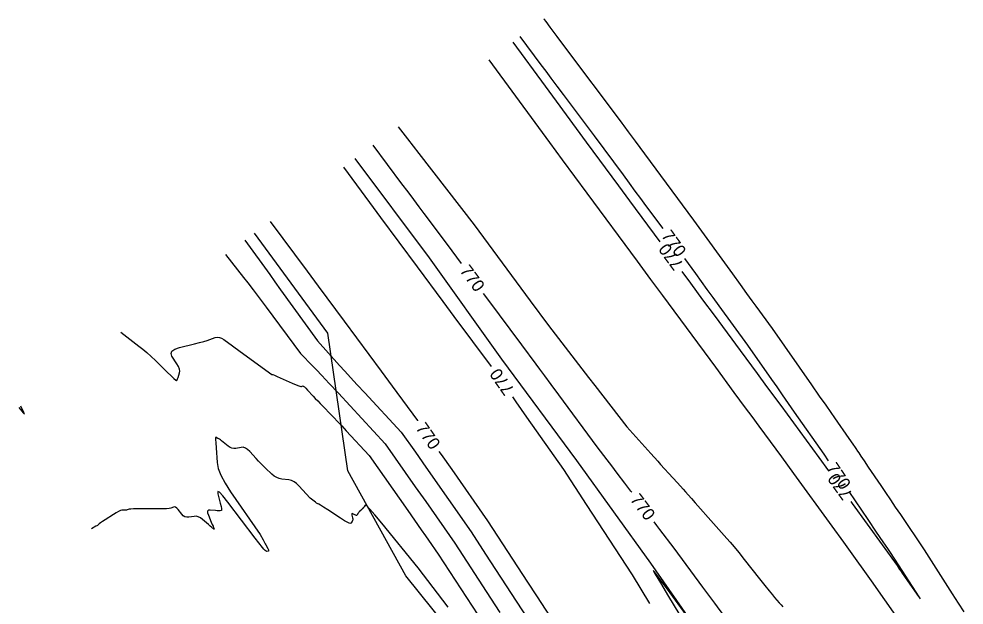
# Model space of a CAD drawing. Extents: x -26 to 1809989, y -25 to 828749.
# Drawn here: x 1809379.9 to 1809760.9, y 828512.9 to 828749.4 of the extents above; entities that cross this region are included whole.
import ezdxf

# ---------------------------------------------------------------- set-up
doc = ezdxf.new("R2010")
doc.units = 0
for name, color, linetype in [('DESIGN - CONTOURS - Index with Text', 7, 'Continuous'), ('DESIGN - CONTOURS - Intermediate with optional Text', 7, 'Continuous'), ('DESIGN - ROW - Slope Lines', 7, 'Continuous')]:
    doc.layers.add(name, color=color, linetype=linetype)

msp = doc.modelspace()

# ---------------------------------------------------------------- linework, layer by layer
at = {"layer": 'DESIGN - CONTOURS - Index with Text'}
for points in [[(1809639.52, 828664.86), (1809632.66, 828674.14), (1809630.55, 828676.99), (1809628.33, 828679.99), (1809626, 828683.15), (1809623.55, 828686.46), (1809611.88, 828702.25), (1809599.43, 828718.89), (1809596.86, 828722.31), (1809594.51, 828725.46), (1809592.37, 828728.32), (1809590.44, 828730.9), (1809581.92, 828742.28)], [(1809578.95, 828740.08), (1809592.04, 828722.22), (1809596.47, 828716.17), (1809608.51, 828699.75), (1809621.52, 828682.13), (1809626.06, 828675.97), (1809638.21, 828659.52)], [(1809558.32, 828650.76), (1809552.67, 828658.4), (1809543.32, 828670.89), (1809541.25, 828673.65), (1809539.07, 828676.57), (1809536.76, 828679.66), (1809534.33, 828682.9), (1809522.71, 828698.43)], [(1809510.72, 828689.54), (1809521.22, 828675.38), (1809525.69, 828669.35), (1809540.5, 828649.38), (1809550.82, 828635.43), (1809555.29, 828629.38), (1809570.23, 828609.18)], [(1809481.24, 828667.71), (1809496.06, 828647.67), (1809500.52, 828641.64), (1809510.97, 828627.51), (1809525.91, 828607.25), (1809530.34, 828601.24), (1809540.53, 828587.41), (1809540.64, 828587.26)], [(1809706.2, 828571.17), (1809704.42, 828573.81), (1809692.56, 828590.78), (1809690.08, 828594.33), (1809687.71, 828597.71), (1809685.47, 828600.93), (1809683.34, 828603.97), (1809673.68, 828617.79), (1809662.19, 828633.65), (1809659.75, 828637.01), (1809657.37, 828640.3), (1809655.04, 828643.52), (1809652.76, 828646.67), (1809648.36, 828652.74)], [(1809647.12, 828647.46), (1809650.59, 828642.76), (1809655.49, 828636.11), (1809660.11, 828629.85), (1809670.57, 828615.69), (1809677.42, 828606.37), (1809681.27, 828601.14), (1809686.95, 828593.42), (1809702.33, 828572.5), (1809706.25, 828567.07), (1809706.37, 828566.91)], [(1809626.92, 828558.46), (1809626.61, 828558.86), (1809625.36, 828560.52), (1809624.16, 828562.1), (1809621.05, 828566.22), (1809619.92, 828567.71), (1809618.87, 828569.09), (1809617.9, 828570.37), (1809617.01, 828571.55), (1809613.03, 828576.81), (1809597.49, 828597.8), (1809594.42, 828601.95), (1809591.88, 828605.38), (1809589.85, 828608.11), (1809588.36, 828610.14), (1809582.59, 828617.93), (1809568.96, 828636.37), (1809567.23, 828638.7)], [(1809578.84, 828596.9), (1809580.17, 828595), (1809584.53, 828588.79), (1809599.39, 828567.6), (1809608.57, 828553.54), (1809627.06, 828525.21), (1809634.11, 828513.59)], [(1809549.23, 828574.97), (1809550.14, 828573.67), (1809554.39, 828567.6), (1809568.83, 828546.94), (1809584.94, 828522.18), (1809588.52, 828516.69), (1809595.77, 828505.55), (1809602.52, 828494.37), (1809604.26, 828491.5)], [(1809715.15, 828554.74), (1809715.71, 828553.98), (1809733.84, 828528.86), (1809734.88, 828527.37), (1809735.24, 828526.84), (1809735.91, 828525.89), (1809736.86, 828524.51), (1809738.11, 828522.71), (1809741.83, 828517.35), (1809742.86, 828515.89), (1809743.16, 828515.53), (1809742.74, 828516.26), (1809741.58, 828518.1), (1809734.49, 828529.24), (1809731.19, 828534.13), (1809730.1, 828535.75), (1809728.23, 828538.52), (1809725.59, 828542.43), (1809722.17, 828547.5), (1809714.59, 828558.73)], [(1809694.95, 828465.75), (1809693.1, 828468.36), (1809685.85, 828478.62), (1809683.41, 828482.08), (1809681.51, 828484.76), (1809680.17, 828486.66), (1809679.37, 828487.79), (1809677.98, 828489.76), (1809677.48, 828490.46), (1809677.03, 828491.1), (1809676.63, 828491.68), (1809676.27, 828492.18), (1809674.7, 828494.4), (1809664.78, 828507.8), (1809662.61, 828510.74), (1809660.36, 828513.79), (1809658.01, 828516.95), (1809655.58, 828520.24), (1809644.02, 828535.87), (1809638.31, 828543.4), (1809637.07, 828545.05), (1809635.97, 828546.5)]]:
    msp.add_lwpolyline(points, dxfattribs=at)
at = {"layer": 'DESIGN - CONTOURS - Intermediate with optional Text'}
for points in [[(1809760.86, 828510.17), (1809758.61, 828513.7), (1809756.24, 828517.43), (1809744.88, 828535.29), (1809735.3, 828549.5), (1809733.27, 828552.51), (1809731.28, 828555.46), (1809729.33, 828558.35), (1809727.42, 828561.17), (1809722.4, 828568.63), (1809720.71, 828571.12), (1809719.43, 828573.02), (1809718.55, 828574.32), (1809718.08, 828575.03), (1809717.35, 828576.11), (1809717.07, 828576.53), (1809716.77, 828576.97), (1809716.46, 828577.43), (1809716.14, 828577.91), (1809714.59, 828580.2), (1809708.81, 828588.48), (1809707.3, 828590.64), (1809705.25, 828593.57), (1809702.65, 828597.28), (1809699.52, 828601.77), (1809683.62, 828624.51), (1809677.13, 828633.48), (1809675.49, 828635.74), (1809673.36, 828638.68), (1809670.74, 828642.3), (1809667.63, 828646.6), (1809651.95, 828668.24), (1809632.15, 828695.01), (1809628.4, 828700.09), (1809625.63, 828703.84), (1809623.84, 828706.26), (1809623.02, 828707.36), (1809621.52, 828709.39), (1809600.78, 828737.11), (1809596.88, 828742.31), (1809594.09, 828746.05), (1809592.39, 828748.32), (1809591.79, 828749.12), (1809591.56, 828749.42)], [(1809569.31, 828732.94), (1809589.35, 828705.6), (1809593.78, 828699.55), (1809598.86, 828692.61), (1809608.85, 828679.08), (1809629.1, 828651.66), (1809634.53, 828644.3), (1809639.26, 828637.9), (1809660.62, 828608.97), (1809668.12, 828598.76), (1809672.69, 828592.55), (1809675.32, 828588.97), (1809678.19, 828585.07), (1809684.94, 828575.9), (1809687.26, 828572.75), (1809692.15, 828566.1), (1809707.55, 828544.79), (1809712.24, 828538.29), (1809714.3, 828535.45), (1809723.43, 828522.8), (1809734.15, 828507.37)], [(1809532.78, 828705.88), (1809536.55, 828701.01), (1809541.14, 828695.07), (1809563.38, 828666.33), (1809586.05, 828635.73), (1809593.42, 828625.78), (1809609.55, 828604.78), (1809612.03, 828601.54), (1809624.89, 828584.82), (1809634.61, 828574.08), (1809637.41, 828570.99), (1809638.56, 828569.71), (1809643.46, 828564.29), (1809645.3, 828562.26), (1809647.61, 828559.71), (1809648.57, 828558.64), (1809649.7, 828557.37), (1809651.02, 828555.89), (1809652.51, 828554.21), (1809659.89, 828545.84), (1809665.27, 828539.86), (1809666.56, 828538.36), (1809668.16, 828536.46), (1809670.05, 828534.13), (1809672.23, 828531.39), (1809678.45, 828523.52), (1809680.58, 828520.84), (1809682.3, 828518.7), (1809683.61, 828517.09), (1809684.52, 828516.03), (1809686.39, 828513.92), (1809687.1, 828513.09), (1809687.85, 828512.2)], [(1809471.03, 828660.15), (1809481.01, 828646.28), (1809483.09, 828643.39), (1809485.39, 828640.19), (1809500.23, 828619.56), (1809509.18, 828609.66), (1809511.25, 828607.37), (1809513.64, 828604.77), (1809516.33, 828601.85), (1809519.33, 828598.6), (1809534.06, 828582.72), (1809539.74, 828574.59), (1809543.96, 828568.55), (1809562.2, 828542.46), (1809568.01, 828533.53), (1809572.03, 828527.36), (1809588.99, 828501.3)], [(1809463.23, 828654.38), (1809470.52, 828645.13), (1809472.26, 828642.9), (1809474.34, 828640.16), (1809476.78, 828636.92), (1809479.57, 828633.17), (1809493.39, 828614.49), (1809498.43, 828609.34), (1809499.89, 828607.82), (1809502.08, 828605.5), (1809505.02, 828602.35), (1809508.69, 828598.39), (1809527.58, 828578.02), (1809539.69, 828560.7), (1809543.89, 828554.69), (1809555.57, 828537.98), (1809570.02, 828515.78), (1809573.82, 828509.95)], [(1809420.97, 828623.08), (1809428.25, 828617.46), (1809429.84, 828616.19), (1809431.49, 828614.78), (1809433.19, 828613.24), (1809434.95, 828611.56), (1809439.73, 828606.91), (1809441.3, 828605.39), (1809442.44, 828604.3), (1809443.14, 828603.65), (1809443.4, 828603.44), (1809443.52, 828603.45), (1809443.59, 828603.54), (1809443.71, 828603.8), (1809443.87, 828604.22), (1809444.08, 828604.8), (1809444.7, 828606.59), (1809444.81, 828607.32), (1809444.67, 828608.17), (1809444.28, 828609.15), (1809443.65, 828610.25), (1809441.64, 828613.35), (1809441.26, 828614.44), (1809441.63, 828615.38), (1809442.76, 828616.17), (1809444.65, 828616.81), (1809450.68, 828618.32), (1809452.76, 828618.86), (1809454.49, 828619.32), (1809455.86, 828619.72), (1809456.87, 828620.05), (1809459.1, 828620.83), (1809459.94, 828621.01), (1809460.79, 828620.95), (1809461.66, 828620.65), (1809462.55, 828620.11), (1809465.98, 828617.59), (1809469.16, 828615.28), (1809481.92, 828606), (1809482.15, 828605.93), (1809482.16, 828605.93), (1809482.16, 828605.93), (1809482.17, 828605.93), (1809482.18, 828605.93), (1809482.18, 828605.93), (1809482.18, 828605.93), (1809482.18, 828605.93), (1809482.17, 828605.96), (1809482.14, 828606), (1809482.35, 828605.91), (1809482.99, 828605.64), (1809484.05, 828605.17), (1809490.12, 828602.51), (1809491.64, 828601.86), (1809492.77, 828601.42), (1809493.52, 828601.18), (1809493.88, 828601.16), (1809494.32, 828601.35), (1809494.57, 828601.31), (1809494.99, 828601.01), (1809495.57, 828600.47), (1809496.32, 828599.68), (1809498.53, 828597.26), (1809499.4, 828596.31), (1809500.36, 828595.3), (1809501.4, 828594.21), (1809502.52, 828593.06), (1809505.63, 828589.88), (1809506.9, 828588.58), (1809508.36, 828587.03), (1809510.03, 828585.26), (1809511.9, 828583.25), (1809521.11, 828573.32), (1809536.63, 828551.12), (1809542.05, 828543.37), (1809543.83, 828540.83), (1809544.98, 828539.17), (1809548.95, 828533.51), (1809564.88, 828509.02)], [(1809379.95, 828592.7), (1809381.72, 828590.45), (1809382.02, 828590.1), (1809382.16, 828590.01), (1809382.13, 828590.18), (1809381.95, 828590.61), (1809380.69, 828593.25)], [(1809552.91, 828512.06), (1809550.77, 828514.89), (1809540.81, 828528.01), (1809526.19, 828546.01), (1809523.43, 828549.35), (1809521.4, 828551.68), (1809520.11, 828552.98), (1809519.56, 828553.25), (1809519.08, 828552.63), (1809518.91, 828552.42), (1809518.79, 828552.26), (1809518.7, 828552.15), (1809518.65, 828552.09), (1809518.57, 828552), (1809518.54, 828551.97), (1809518.51, 828551.94), (1809518.48, 828551.9), (1809518.39, 828551.79), (1809518.33, 828551.73), (1809518.22, 828551.62), (1809518.05, 828551.45), (1809517.82, 828551.22), (1809517.13, 828550.54), (1809516.91, 828550.31), (1809516.74, 828550.13), (1809516.63, 828550.01), (1809516.58, 828549.93), (1809516.53, 828549.79), (1809516.51, 828549.74), (1809516.47, 828549.67), (1809516.42, 828549.58), (1809516.35, 828549.49), (1809516.16, 828549.22), (1809516.06, 828549.16), (1809515.9, 828549.16), (1809515.67, 828549.22), (1809515.39, 828549.35), (1809514.54, 828549.79), (1809514.28, 828549.88), (1809514.12, 828549.83), (1809514.06, 828549.62), (1809514.12, 828549.27), (1809514.4, 828548.13), (1809514.47, 828547.72), (1809514.46, 828547.35), (1809514.38, 828547.02), (1809514.23, 828546.73), (1809513.73, 828546), (1809513.33, 828545.92), (1809512.49, 828546.22), (1809511.22, 828546.91), (1809509.53, 828547.99), (1809504.42, 828551.38), (1809502.74, 828552.48), (1809501.54, 828553.27), (1809500.8, 828553.73), (1809500.54, 828553.86), (1809500.47, 828553.78), (1809500.39, 828553.8), (1809500.19, 828553.91), (1809499.89, 828554.12), (1809499.47, 828554.42), (1809497.27, 828556.03), (1809492.82, 828561.04), (1809491.85, 828561.99), (1809490.86, 828562.71), (1809489.83, 828563.19), (1809488.78, 828563.43), (1809485.95, 828563.75), (1809484.9, 828563.96), (1809483.87, 828564.38), (1809482.87, 828564.99), (1809481.89, 828565.79), (1809479.32, 828568.21), (1809478.36, 828569.13), (1809477.41, 828570.08), (1809476.46, 828571.07), (1809475.52, 828572.09), (1809473.03, 828574.85), (1809472.11, 828575.74), (1809471.23, 828576.32), (1809470.37, 828576.61), (1809469.54, 828576.59), (1809467.38, 828576.14), (1809466.58, 828576.07), (1809465.79, 828576.19), (1809465.03, 828576.51), (1809464.28, 828577.03), (1809462.32, 828578.67), (1809461.66, 828579.22), (1809461.15, 828579.62), (1809460.79, 828579.88), (1809460.58, 828580.01), (1809460.22, 828580.14), (1809460.09, 828580.2), (1809459.96, 828580.27), (1809459.82, 828580.34), (1809459.69, 828580.43), (1809459.33, 828580.67), (1809459.24, 828580.47), (1809459.22, 828579.69), (1809459.27, 828578.34), (1809459.4, 828576.41), (1809459.84, 828570.5), (1809460.31, 828568.1), (1809461.37, 828565.33), (1809463.02, 828562.19), (1809465.27, 828558.68), (1809477.14, 828541.43), (1809478.37, 828539.22), (1809478.63, 828538.74), (1809478.91, 828538.25), (1809479.19, 828537.73), (1809479.48, 828537.2), (1809480.26, 828535.77), (1809480.49, 828535.29), (1809480.59, 828534.95), (1809480.56, 828534.73), (1809480.4, 828534.64), (1809479.81, 828534.58), (1809479.54, 828534.67), (1809479.16, 828534.96), (1809478.68, 828535.46), (1809478.09, 828536.17), (1809475.13, 828539.97), (1809464.13, 828554.52), (1809462.12, 828557.07), (1809460.78, 828558.48), (1809460.13, 828558.75), (1809460.15, 828557.88), (1809461.12, 828554.05), (1809461.42, 828552.78), (1809461.59, 828551.87), (1809461.62, 828551.3), (1809461.53, 828551.08), (1809461.1, 828550.97), (1809460.86, 828550.94), (1809460.46, 828550.95), (1809459.89, 828550.98), (1809459.17, 828551.05), (1809457.01, 828551.26), (1809456.36, 828551.2), (1809456.02, 828550.85), (1809456, 828550.21), (1809456.29, 828549.28), (1809457.49, 828546.43), (1809457.89, 828545.48), (1809458.18, 828544.76), (1809458.38, 828544.28), (1809458.47, 828544.04), (1809458.58, 828543.71), (1809458.6, 828543.61), (1809458.59, 828543.56), (1809458.55, 828543.56), (1809458.47, 828543.6), (1809458.22, 828543.8), (1809458.03, 828543.96), (1809457.65, 828544.29), (1809457.07, 828544.79), (1809456.29, 828545.46), (1809453.97, 828547.47), (1809453.1, 828548.12), (1809452.25, 828548.55), (1809451.41, 828548.76), (1809450.58, 828548.75), (1809448.39, 828548.43), (1809447.6, 828548.41), (1809446.88, 828548.6), (1809446.21, 828549), (1809445.61, 828549.59), (1809444.09, 828551.46), (1809443.55, 828552.05), (1809443.05, 828552.43), (1809442.6, 828552.58), (1809442.2, 828552.51), (1809441.19, 828552.04), (1809440.57, 828551.89), (1809439.47, 828551.79), (1809437.9, 828551.73), (1809435.84, 828551.73), (1809429.71, 828551.77), (1809427.66, 828551.78), (1809426.1, 828551.75), (1809425.03, 828551.7), (1809424.45, 828551.63), (1809423.56, 828551.38), (1809423.25, 828551.3), (1809422.99, 828551.25), (1809422.77, 828551.23), (1809422.59, 828551.23), (1809422.19, 828551.28), (1809422.03, 828551.29), (1809421.87, 828551.28), (1809421.68, 828551.26), (1809421.49, 828551.23), (1809420.96, 828551.11), (1809420.63, 828550.97), (1809420.04, 828550.65), (1809419.19, 828550.14), (1809418.07, 828549.44), (1809414.75, 828547.34), (1809413.65, 828546.64), (1809412.84, 828546.11), (1809412.32, 828545.76), (1809412.1, 828545.58), (1809411.89, 828545.34), (1809411.77, 828545.24), (1809411.58, 828545.1), (1809411.31, 828544.94), (1809410.97, 828544.74), (1809409.21, 828543.74)], [(1809648.92, 828509.07), (1809641.31, 828519.36), (1809640.01, 828521.12), (1809638.86, 828522.67), (1809636.01, 828526.52), (1809635.57, 828526.96), (1809636.38, 828525.42), (1809638.45, 828521.89), (1809641.77, 828516.37), (1809660.21, 828485.96)]]:
    msp.add_lwpolyline(points, dxfattribs=at)
at = {"layer": 'DESIGN - ROW - Slope Lines'}
for p, q in [((1809545.37, 828652.99), (1809515.51, 828693.1)), ((1809504.41, 828622.66), (1809474.91, 828663.02)), ((1809574.61, 828612.13), (1809545.37, 828652.99)), ((1809512.55, 828567.11), (1809504.41, 828622.66)), ((1809604.84, 828571.28), (1809574.61, 828612.13)), ((1809634.57, 828529.93), (1809604.84, 828571.28)), ((1809535.92, 828524.7), (1809512.55, 828567.11)), ((1809663.79, 828488.05), (1809634.57, 828529.93)), ((1809566.33, 828487.06), (1809535.92, 828524.7))]:
    msp.add_line(p, q, dxfattribs=at)

# ---------------------------------------------------------------- texts
at = {"layer": 'DESIGN - CONTOURS - Index with Text'}
for rotation, p in [(306.0938, (1809638.61, 828661.91)), (126.4395, (1809648.03, 828650.42)), (306.4789, (1809557.4, 828647.79)), (125.0594, (1809579.83, 828599.85)), (304.9641, (1809539.64, 828584.32)), (304.0041, (1809705.16, 828568.24)), (125.834, (1809716.1, 828557.7)), (307.1222, (1809626.03, 828555.48))]:
    msp.add_text('770', height=5, rotation=rotation, dxfattribs=at).set_placement(p)

doc.saveas('drawing.dxf')
